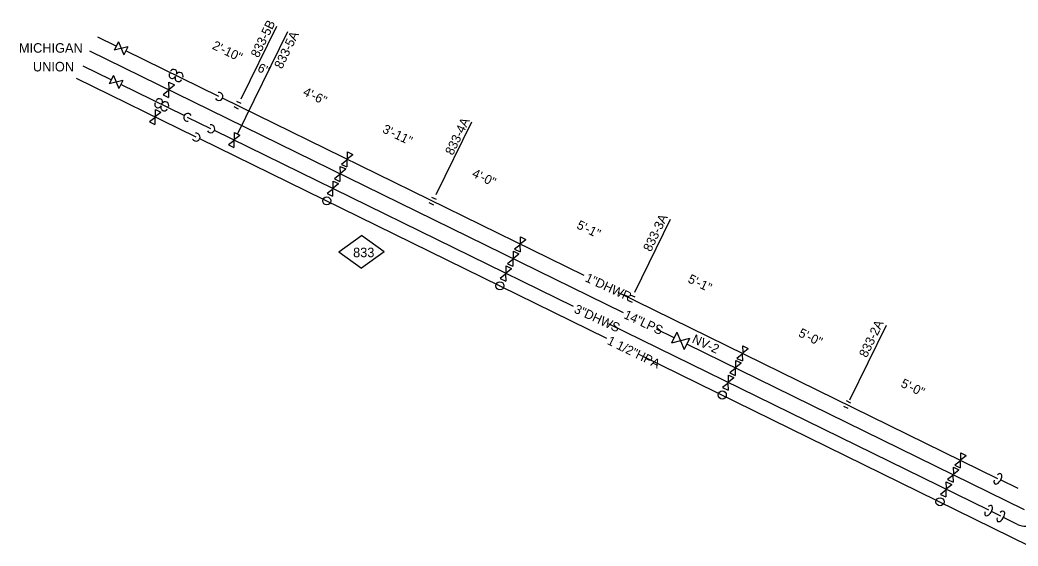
# Model space of a CAD drawing. Extents: x 9888 to 10178, y 10284 to 10314.
# Drawn here: x 9887.86 to 9928.84, y 10288.59 to 10310.18 of the extents above; entities that cross this region are included whole.
import ezdxf

# ---------------------------------------------------------------- set-up
doc = ezdxf.new("R2010")
doc.units = 0
for name, color, linetype in [('Level 51', 7, 'Continuous'), ('Level 55', 7, 'Continuous'), ('M-ANNO-NPLT', 7, 'Continuous'), ('M-HVAC-SUPP-N', 7, 'Continuous'), ('M-PROC-PIPE', 7, 'Continuous'), ('M-STEM-CONP', 7, 'Continuous'), ('M-STEM-CONP-N', 7, 'Continuous'), ('P-CMPA-PIPE', 7, 'Continuous'), ('P-DOMW-HPIP', 7, 'Continuous'), ('P-DOMW-HPIP-N', 7, 'Continuous')]:
    doc.layers.add(name, color=color, linetype=linetype)

msp = doc.modelspace()

# ---------------------------------------------------------------- linework, layer by layer
at = {"layer": 'Level 51'}
for p, q in [((9900.954, 10300.663), (9901.887, 10301.335)), ((9902.82, 10300.663), (9901.887, 10301.335)), ((9900.954, 10300.663), (9901.887, 10299.99)), ((9902.82, 10300.663), (9901.887, 10299.99))]:
    msp.add_line(p, q, dxfattribs=at)
at = {"layer": 'Level 55'}
for p, q in [((9891.816, 10309.11), (9891.063, 10309.479)), ((9891.905, 10309.283), (9891.733, 10308.949)), ((9891.905, 10309.283), (9892.122, 10308.749)), ((9892.294, 10309.083), (9891.733, 10308.949)), ((9892.294, 10309.083), (9892.122, 10308.749))]:
    msp.add_line(p, q, dxfattribs=at)
at = {"layer": 'M-ANNO-NPLT'}
for p, q in [((9898.843, 10309.693), (9896.778, 10305.484)), ((9898.394, 10309.913), (9896.93, 10306.928)), ((9906.4, 10305.987), (9904.936, 10303.002)), ((9914.555, 10301.988), (9913.091, 10299.003)), ((9923.418, 10297.641), (9921.913, 10294.573))]:
    msp.add_line(p, q, dxfattribs=at)
at = {"layer": 'M-PROC-PIPE'}
for p, q in [((9896.028, 10307.043), (9892.208, 10308.916)), ((9911.022, 10299.689), (9896.176, 10306.97)), ((9901.311, 10304.49), (9901.305, 10304.767)), ((9901.305, 10304.767), (9901.529, 10304.661)), ((9901.311, 10304.49), (9901.529, 10304.661)), ((9901.281, 10304.427), (9901.063, 10304.256)), ((9901.063, 10304.256), (9901.287, 10304.15)), ((9901.281, 10304.427), (9901.287, 10304.15)), ((9908.389, 10300.942), (9908.171, 10300.771)), ((9908.389, 10300.942), (9908.395, 10300.665)), ((9908.419, 10301.004), (9908.413, 10301.281)), ((9908.413, 10301.281), (9908.637, 10301.175)), ((9908.419, 10301.004), (9908.637, 10301.175)), ((9908.171, 10300.771), (9908.395, 10300.665)), ((9928.013, 10291.356), (9912.425, 10299.001)), ((9917.517, 10296.465), (9917.299, 10296.294)), ((9917.517, 10296.465), (9917.523, 10296.188)), ((9917.547, 10296.528), (9917.541, 10296.805)), ((9917.541, 10296.805), (9917.765, 10296.699)), ((9917.547, 10296.528), (9917.765, 10296.699)), ((9917.299, 10296.294), (9917.523, 10296.188)), ((9926.488, 10292.143), (9926.482, 10292.42)), ((9926.482, 10292.42), (9926.706, 10292.314)), ((9926.488, 10292.143), (9926.706, 10292.314)), ((9926.458, 10292.08), (9926.24, 10291.909)), ((9926.24, 10291.909), (9926.464, 10291.803)), ((9926.458, 10292.08), (9926.464, 10291.803)), ((9928.837, 10290.952), (9928.122, 10291.303))]:
    msp.add_line(p, q, dxfattribs=at)
for centre, radius, start, end in [((9894.124, 10307.921), 0.14, 153.3618, 333.3618), ((9894.171, 10308.015), 0.14, 333.3618, 153.3618), ((9894.421, 10307.891), 0.14, 333.3618, 153.3618), ((9894.373, 10307.795), 0.14, 153.3618, 333.3618), ((9896.028, 10307.043), 0.164, 209.9138, 97.7117)]:
    msp.add_arc(centre, radius, start, end, dxfattribs=at)
msp.add_ellipse((9928.009, 10291.349), major_axis=(-0.123, -0.205), ratio=0.503291, start_param=5.263815, end_param=10.432096, dxfattribs=at)
at = {"layer": 'M-STEM-CONP'}
for p, q in [((9912.634, 10298.156), (9890.734, 10308.897)), ((9893.985, 10307.347), (9893.979, 10307.624)), ((9893.979, 10307.624), (9894.203, 10307.518)), ((9893.985, 10307.347), (9894.203, 10307.518)), ((9893.956, 10307.284), (9893.738, 10307.113)), ((9893.738, 10307.113), (9893.962, 10307.007)), ((9893.956, 10307.284), (9893.962, 10307.007)), ((9896.948, 10306.748), (9896.765, 10306.838)), ((9896.838, 10306.524), (9896.655, 10306.613)), ((9900.989, 10303.835), (9900.771, 10303.664)), ((9900.989, 10303.835), (9900.995, 10303.558)), ((9901.018, 10303.897), (9901.012, 10304.174)), ((9901.012, 10304.174), (9901.236, 10304.068)), ((9901.018, 10303.897), (9901.236, 10304.068)), ((9900.771, 10303.664), (9900.995, 10303.558)), ((9904.852, 10302.585), (9904.669, 10302.675)), ((9904.962, 10302.81), (9904.779, 10302.899)), ((9908.126, 10300.412), (9908.12, 10300.688)), ((9908.12, 10300.688), (9908.344, 10300.583)), ((9908.126, 10300.412), (9908.344, 10300.583)), ((9908.097, 10300.349), (9907.879, 10300.178)), ((9907.879, 10300.178), (9908.103, 10300.072)), ((9908.097, 10300.349), (9908.103, 10300.072)), ((9913.115, 10298.804), (9912.931, 10298.894)), ((9913.005, 10298.58), (9912.821, 10298.669)), ((9914.718, 10297.135), (9913.996, 10297.489)), ((9929.106, 10290.078), (9915.239, 10296.879)), ((9917.254, 10295.935), (9917.248, 10296.212)), ((9917.248, 10296.212), (9917.472, 10296.106)), ((9917.254, 10295.935), (9917.472, 10296.106)), ((9917.225, 10295.872), (9917.007, 10295.701)), ((9917.007, 10295.701), (9917.231, 10295.595)), ((9917.225, 10295.872), (9917.231, 10295.595)), ((9921.977, 10294.458), (9921.794, 10294.547)), ((9921.867, 10294.233), (9921.684, 10294.323)), ((9926.166, 10291.487), (9925.948, 10291.316)), ((9926.166, 10291.487), (9926.172, 10291.21)), ((9926.195, 10291.55), (9926.189, 10291.827)), ((9926.189, 10291.827), (9926.413, 10291.721)), ((9926.195, 10291.55), (9926.413, 10291.721)), ((9925.948, 10291.316), (9926.172, 10291.21))]:
    msp.add_line(p, q, dxfattribs=at)
at = {"layer": 'M-STEM-CONP-N'}
for p, q in [((9914.831, 10297.365), (9914.606, 10296.918)), ((9914.831, 10297.365), (9915.126, 10296.655)), ((9915.352, 10297.103), (9914.606, 10296.918)), ((9915.352, 10297.103), (9915.126, 10296.655))]:
    msp.add_line(p, q, dxfattribs=at)
at = {"layer": 'P-CMPA-PIPE'}
for p, q in [((9895.094, 10305.374), (9890.186, 10307.781)), ((9893.432, 10306.23), (9893.426, 10306.507)), ((9893.426, 10306.507), (9893.65, 10306.401)), ((9893.432, 10306.23), (9893.65, 10306.401)), ((9893.402, 10306.167), (9893.184, 10305.996)), ((9893.184, 10305.996), (9893.408, 10305.89)), ((9893.402, 10306.167), (9893.408, 10305.89)), ((9911.954, 10297.105), (9895.242, 10305.301)), ((9929.314, 10288.592), (9913.444, 10296.374))]:
    msp.add_line(p, q, dxfattribs=at)
for centre in [(9900.459, 10302.756), (9907.567, 10299.27), (9916.695, 10294.793), (9925.636, 10290.408)]:
    msp.add_circle(centre, 0.167, dxfattribs=at)
msp.add_arc((9895.094, 10305.374), 0.164, 209.9138, 97.7117, dxfattribs=at)
at = {"layer": 'P-DOMW-HPIP'}
for p, q in [((9891.61, 10307.724), (9890.464, 10308.286)), ((9891.7, 10307.898), (9891.528, 10307.564)), ((9891.7, 10307.898), (9891.917, 10307.365)), ((9892.089, 10307.699), (9891.528, 10307.564)), ((9892.089, 10307.699), (9891.917, 10307.365))]:
    msp.add_line(p, q, dxfattribs=at)
at = {"layer": 'P-DOMW-HPIP-N'}
for p, q in [((9894.601, 10306.257), (9892.003, 10307.532)), ((9895.699, 10305.719), (9894.749, 10306.185)), ((9910.585, 10298.418), (9895.847, 10305.646)), ((9896.673, 10305.286), (9896.667, 10305.563)), ((9896.667, 10305.563), (9896.891, 10305.457)), ((9896.673, 10305.286), (9896.891, 10305.457)), ((9896.643, 10305.223), (9896.425, 10305.052)), ((9896.425, 10305.052), (9896.649, 10304.946)), ((9896.643, 10305.223), (9896.649, 10304.946)), ((9900.722, 10303.294), (9900.716, 10303.571)), ((9900.716, 10303.571), (9900.94, 10303.465)), ((9900.722, 10303.294), (9900.94, 10303.465)), ((9900.692, 10303.231), (9900.474, 10303.06)), ((9900.474, 10303.06), (9900.698, 10302.954)), ((9900.692, 10303.231), (9900.698, 10302.954)), ((9907.8, 10299.745), (9907.582, 10299.574)), ((9907.8, 10299.745), (9907.806, 10299.468)), ((9907.83, 10299.808), (9907.824, 10300.085)), ((9907.824, 10300.085), (9908.048, 10299.979)), ((9907.83, 10299.808), (9908.048, 10299.979)), ((9907.582, 10299.574), (9907.806, 10299.468)), ((9927.635, 10290.057), (9912.027, 10297.712)), ((9916.958, 10295.332), (9916.952, 10295.608)), ((9916.952, 10295.608), (9917.176, 10295.502)), ((9916.928, 10295.269), (9916.71, 10295.098)), ((9916.928, 10295.269), (9916.934, 10294.992)), ((9916.958, 10295.332), (9917.176, 10295.502)), ((9916.71, 10295.098), (9916.934, 10294.992)), ((9925.899, 10290.947), (9925.893, 10291.224)), ((9925.893, 10291.224), (9926.117, 10291.118)), ((9925.899, 10290.947), (9926.117, 10291.118)), ((9925.869, 10290.884), (9925.651, 10290.713)), ((9925.651, 10290.713), (9925.875, 10290.607)), ((9925.869, 10290.884), (9925.875, 10290.607)), ((9928.133, 10289.813), (9927.744, 10290.003)), ((9928.814, 10289.478), (9928.241, 10289.759))]:
    msp.add_line(p, q, dxfattribs=at)
for centre, radius, start, end in [((9893.536, 10306.718), 0.14, 153.3618, 333.3618), ((9893.583, 10306.812), 0.14, 333.3618, 153.3618), ((9893.786, 10306.592), 0.14, 153.3618, 333.3618), ((9893.833, 10306.687), 0.14, 333.3618, 153.3618), ((9894.749, 10306.185), 0.164, 29.9138, 277.7117), ((9895.699, 10305.719), 0.164, 209.9138, 97.7117), ((9929.145, 10290.152), 0.75, 243.8756, 271.9385)]:
    msp.add_arc(centre, radius, start, end, dxfattribs=at)
for centre in [(9927.63, 10290.046), (9928.129, 10289.806)]:
    msp.add_ellipse(centre, major_axis=(-0.123, -0.205), ratio=0.503291, start_param=5.263815, end_param=10.432096, dxfattribs=at)

# ---------------------------------------------------------------- texts
at = {"layer": 'Level 51'}
for s, p in [('MICHIGAN ', (9887.822, 10308.838)), ('UNION', (9888.397, 10308.071)), ('833', (9901.541, 10300.445))]:
    msp.add_text(s, height=0.3915, dxfattribs=at).set_placement(p)
at = {"layer": 'Level 55'}
msp.add_text('1"DHWR', height=0.375, rotation=335.2311, dxfattribs=at).set_placement((9911.033, 10299.468))
at = {"layer": 'M-HVAC-SUPP-N'}
for s, rotation, p in [('833-5B', 64.2493, (9897.655, 10308.605)), ('833-5A', 64.2493, (9898.62, 10308.145)), ('2\'-10"', 334.2493, (9895.728, 10309.01)), ('6"', 334.2493, (9897.583, 10308.094)), ('4\'-6"', 334.2493, (9899.451, 10307.109)), ('3\'-11"', 334.2493, (9902.711, 10305.581)), ('833-4A', 64.2493, (9905.635, 10304.601)), ('4\'-0"', 334.2493, (9906.391, 10303.762)), ('5\'-1"', 334.2493, (9910.686, 10301.644)), ('833-3A', 64.2493, (9913.764, 10300.642)), ('5\'-1"', 334.2493, (9915.252, 10299.428)), ('833-2A', 64.2493, (9922.626, 10296.295)), ('5\'-0"', 334.2493, (9919.792, 10297.212)), ('5\'-0"', 334.2493, (9923.99, 10295.144))]:
    msp.add_text(s, height=0.375, rotation=rotation, dxfattribs=at).set_placement(p)
at = {"layer": 'M-STEM-CONP'}
for s, p in [('14"LPS', (9912.621, 10297.954)), ('NV-2', (9915.422, 10296.955))]:
    msp.add_text(s, height=0.375, rotation=335.2311, dxfattribs=at).set_placement(p)
at = {"layer": 'P-CMPA-PIPE'}
msp.add_text('1 1/2"HPA', height=0.375, rotation=333.8755, dxfattribs=at).set_placement((9911.939, 10296.892))
at = {"layer": 'P-DOMW-HPIP'}
msp.add_text('3"DHWS', height=0.375, rotation=335.2311, dxfattribs=at).set_placement((9910.579, 10298.187))

doc.saveas('drawing.dxf')
